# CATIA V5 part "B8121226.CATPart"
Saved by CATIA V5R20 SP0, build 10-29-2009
Part number: B8121226
Revision: 3
Definition: design
Nomenclature: B8121226
Source: made
Description: NOT SPECIFIED
Bounding box of the stored display mesh (mm): x -13 to 13, y -13 to 13, z -6 to 20
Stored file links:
  C:\Users\Utente\Desktop\3D files B812\B8121226.CATPart
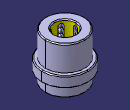
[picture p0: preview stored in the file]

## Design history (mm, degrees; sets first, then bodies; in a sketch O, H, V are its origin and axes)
Body1 "MANIFOLD_SOLID_BREP #38" (main body)
  Solid1: solid without history
Body2 "MANIFOLD_SOLID_BREP #76"
  Solid2: solid without history
Body3 "MANIFOLD_SOLID_BREP #114"
  Solid3: solid without history
Body4 "MANIFOLD_SOLID_BREP #152"
  Solid4: solid without history
Body5 "MANIFOLD_SOLID_BREP #190"
  Solid5: solid without history
Body6 "MANIFOLD_SOLID_BREP #228"
  Solid6: solid without history
Body7 "MANIFOLD_SOLID_BREP #266"
  Solid7: solid without history
Body8 "MANIFOLD_SOLID_BREP #304"
  Solid8: solid without history
Body9 "MANIFOLD_SOLID_BREP #1974"
  Solid9: solid without history
Body10 "MANIFOLD_SOLID_BREP #2012"
  Solid10: solid without history
Body11 "MANIFOLD_SOLID_BREP #2050"
  Solid11: solid without history
Body12 "MANIFOLD_SOLID_BREP #2088"
  Solid12: solid without history
Body13 "MANIFOLD_SOLID_BREP #2126"
  Solid13: solid without history
Body14 "MANIFOLD_SOLID_BREP #2164"
  Solid14: solid without history
Body15 "MANIFOLD_SOLID_BREP #2202"
  Solid15: solid without history
Body16 "MANIFOLD_SOLID_BREP #2240"
  Solid16: solid without history
Body17 "MANIFOLD_SOLID_BREP #2278"
  Solid17: solid without history
Body18 "MANIFOLD_SOLID_BREP #2316"
  Solid18: solid without history
Body19 "MANIFOLD_SOLID_BREP #2354"
  Solid19: solid without history
Body20 "MANIFOLD_SOLID_BREP #2392"
  Solid20: solid without history
Body21 "MANIFOLD_SOLID_BREP #2430"
  Solid21: solid without history
Body22 "MANIFOLD_SOLID_BREP #2468"
  Solid22: solid without history
Body23 "MANIFOLD_SOLID_BREP #2506"
  Solid23: solid without history
Body24 "MANIFOLD_SOLID_BREP #2544"
  Solid24: solid without history
Body25 "MANIFOLD_SOLID_BREP #2582"
  Solid25: solid without history
Body26 "MANIFOLD_SOLID_BREP #2620"
  Solid26: solid without history
Body27 "MANIFOLD_SOLID_BREP #2658"
  Solid27: solid without history
Body28 "MANIFOLD_SOLID_BREP #2696"
  Solid28: solid without history
Body29 "MANIFOLD_SOLID_BREP #2734"
  Solid29: solid without history
Body30 "MANIFOLD_SOLID_BREP #2772"
  Solid30: solid without history
Body31 "MANIFOLD_SOLID_BREP #2810"
  Solid31: solid without history
Body32 "MANIFOLD_SOLID_BREP #2848"
  Solid32: solid without history
Body33 "MANIFOLD_SOLID_BREP #2886"
  Solid33: solid without history
Body34 "MANIFOLD_SOLID_BREP #2924"
  Solid34: solid without history
Body35 "MANIFOLD_SOLID_BREP #2962"
  Solid35: solid without history
Body36 "MANIFOLD_SOLID_BREP #3000"
  Solid36: solid without history
Body37 "MANIFOLD_SOLID_BREP #3038"
  Solid37: solid without history
Body38 "MANIFOLD_SOLID_BREP #3076"
  Solid38: solid without history
Body39 "MANIFOLD_SOLID_BREP #3114"
  Solid39: solid without history
Body40 "MANIFOLD_SOLID_BREP #3152"
  Solid40: solid without history
Body41 "MANIFOLD_SOLID_BREP #3190"
  Solid41: solid without history
Body42 "MANIFOLD_SOLID_BREP #3228"
  Solid42: solid without history
Body43 "MANIFOLD_SOLID_BREP #3266"
  Solid43: solid without history
Body44 "MANIFOLD_SOLID_BREP #3304"
  Solid44: solid without history
Body45 "MANIFOLD_SOLID_BREP #3342"
  Solid45: solid without history
Body46 "MANIFOLD_SOLID_BREP #3380"
  Solid46: solid without history
Body47 "MANIFOLD_SOLID_BREP #3418"
  Solid47: solid without history
Body48 "MANIFOLD_SOLID_BREP #3456"
  Solid48: solid without history
Body49 "MANIFOLD_SOLID_BREP #3494"
  Solid49: solid without history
